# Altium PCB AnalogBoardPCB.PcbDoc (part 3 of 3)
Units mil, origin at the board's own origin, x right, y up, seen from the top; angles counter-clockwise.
Board outline 5875 x 2550 mil, 4 copper layers (Top Layer, GND, VCC, Bottom Layer); 569 components, 22 nets, 1336 pads, 360 vias.
Unrouted connection lines stored in the file: 31.
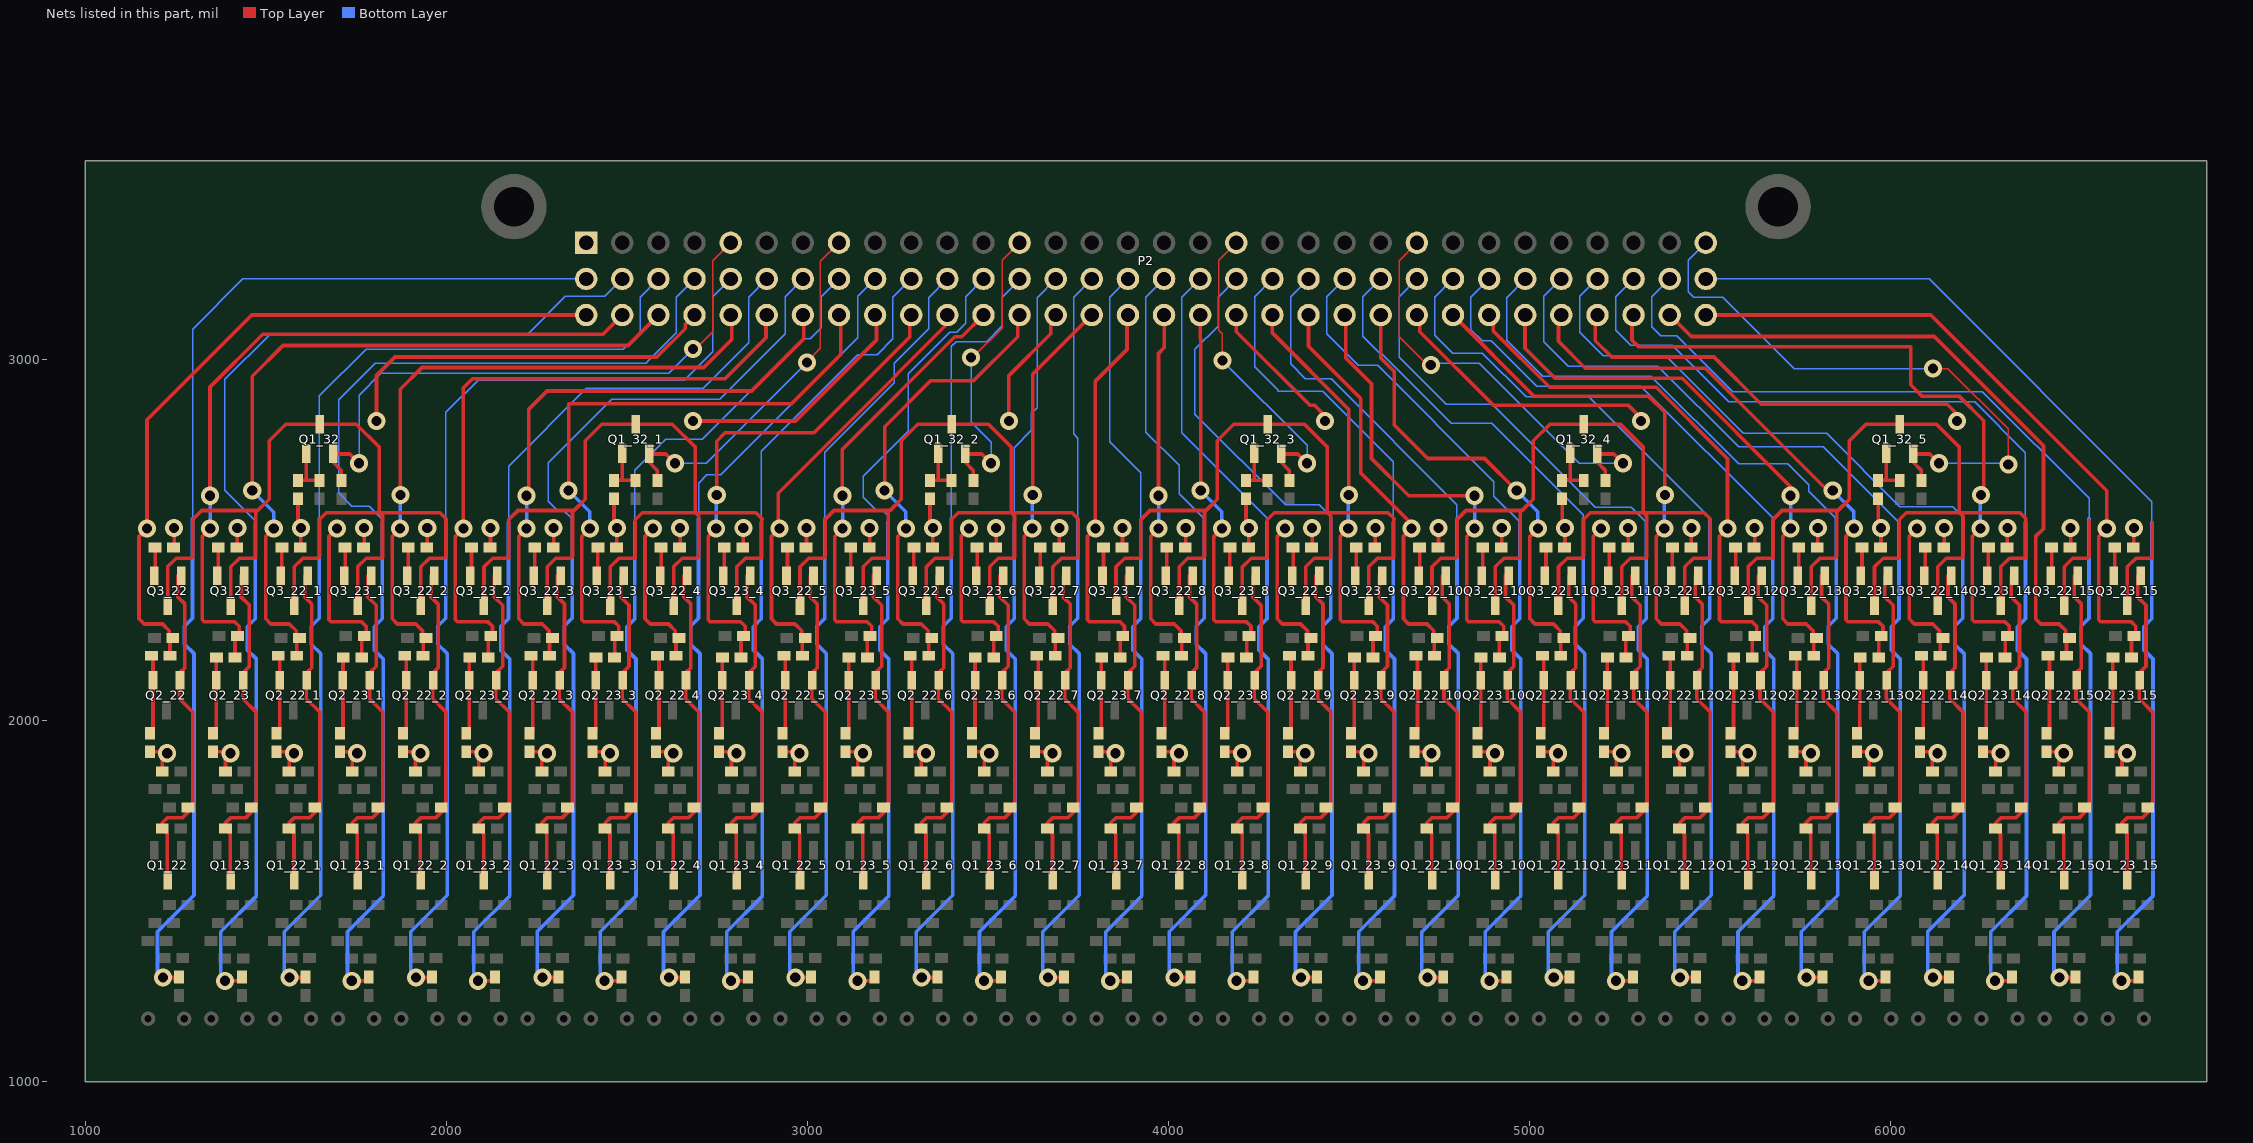
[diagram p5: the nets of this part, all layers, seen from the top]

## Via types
v1: diameter 50, hole 28, Top Layer to Bottom Layer, 327 vias
v2: diameter 50, hole 28, Top Layer to Bottom Layer, tented top, 31 vias
v3: diameter 50, hole 28, Top Layer to Bottom Layer, tented both sides, 2 vias

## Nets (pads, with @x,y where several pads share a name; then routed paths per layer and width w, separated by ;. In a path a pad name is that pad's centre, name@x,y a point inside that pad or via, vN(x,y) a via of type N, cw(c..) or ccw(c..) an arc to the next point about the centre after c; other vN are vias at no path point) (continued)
NetC4_1: C4_22.1 C4_22_1.1 C4_22_2.1 C4_22_3.1 C4_22_4.1 C4_22_5.1 C4_22_6.1 C4_22_7.1 C4_22_8.1 C4_22_9.1 C4_22_10.1 C4_22_11.1 C4_22_12.1 C4_22_13.1 C4_22_14.1 C4_22_15.1 C4_23.1 C4_23_1.1 C4_23_2.1 C4_23_3.1 C4_23_4.1 C4_23_5.1 C4_23_6.1 C4_23_7.1 C4_23_8.1 C4_23_9.1 C4_23_10.1 C4_23_11.1 C4_23_12.1 C4_23_13.1 C4_23_14.1 C4_23_15.1 Q2_22.2 Q2_22_1.2 Q2_22_2.2 Q2_22_3.2 Q2_22_4.2 Q2_22_5.2 Q2_22_6.2 Q2_22_7.2 Q2_22_8.2 Q2_22_9.2 Q2_22_10.2 Q2_22_11.2 Q2_22_12.2 Q2_22_13.2 Q2_22_14.2 Q2_22_15.2 Q2_23.2 Q2_23_1.2 Q2_23_2.2 Q2_23_3.2 Q2_23_4.2 Q2_23_5.2 Q2_23_6.2 Q2_23_7.2 Q2_23_8.2 Q2_23_9.2 Q2_23_10.2 Q2_23_11.2 Q2_23_12.2 Q2_23_13.2 Q2_23_14.2 Q2_23_15.2 R4_22.1 R4_22_1.1 R4_22_2.1 R4_22_3.1 R4_22_4.1 R4_22_5.1 R4_22_6.1 R4_22_7.1 R4_22_8.1 R4_22_9.1 R4_22_10.1 R4_22_11.1 R4_22_12.1 R4_22_13.1 R4_22_14.1 R4_22_15.1 R4_23.1 R4_23_1.1 R4_23_2.1 R4_23_3.1 R4_23_4.1 R4_23_5.1 R4_23_6.1 R4_23_7.1 R4_23_8.1 R4_23_9.1 R4_23_10.1 R4_23_11.1 R4_23_12.1 R4_23_13.1 R4_23_14.1 R4_23_15.1 | length 6080
  Top Layer w10: R4_22.1@1188.1,1973.19 1188.1,2163.19 ; R4_23.1@1363.1,1973.19 C4_23.1@1363.1,2163.19 ; R4_22_1.1@1539.1,1973.19 1539.1,2163.19 ; R4_23_1.1@1714.1,1973.19 C4_23_1.1@1714.1,2163.19 ; R4_22_2.1@1889.1,1973.19 1889.1,2163.19 ; R4_23_2.1@2064.1,1973.19 C4_23_2.1@2064.1,2163.19 ; R4_22_3.1@2239.1,1973.19 2239.1,2163.19 ; R4_23_3.1@2414.1,1973.19 C4_23_3.1@2414.1,2163.19 ; R4_22_4.1@2589.1,1973.19 2589.1,2163.19 ; R4_23_4.1@2764.1,1973.19 C4_23_4.1@2764.1,2163.19 ; R4_22_5.1@2939.1,1973.19 2939.1,2163.19 ; R4_23_5.1@3114.1,1973.19 C4_23_5.1@3114.1,2163.19 ; R4_22_6.1@3289.1,1973.19 3289.1,2163.19 ; R4_23_6.1@3464.1,1973.19 C4_23_6.1@3464.1,2163.19 ; R4_22_7.1@3639.1,1973.19 3639.1,2163.19 ; R4_23_7.1@3814.1,1973.19 C4_23_7.1@3814.1,2163.19 ; R4_22_8.1@3989.1,1973.19 3989.1,2163.19 ; R4_23_8.1@4164.1,1973.19 C4_23_8.1@4164.1,2163.19 ; R4_22_9.1@4339.1,1973.19 4339.1,2163.19 ; R4_23_9.1@4514.1,1973.19 C4_23_9.1@4514.1,2163.19 ; R4_22_10.1@4689.1,1973.19 4689.1,2163.19 ; R4_23_10.1@4864.1,1973.19 C4_23_10.1@4864.1,2163.19 ; R4_22_11.1@5039.1,1973.19 5039.1,2163.19 ; R4_23_11.1@5214.1,1973.19 C4_23_11.1@5214.1,2163.19 ; R4_22_12.1@5389.1,1973.19 5389.1,2163.19 ; R4_23_12.1@5564.1,1973.19 C4_23_12.1@5564.1,2163.19 ; R4_22_13.1@5739.1,1973.19 5739.1,2163.19 ; R4_23_13.1@5914.1,1973.19 C4_23_13.1@5914.1,2163.19 ; R4_22_14.1@6089.1,1973.19 6089.1,2163.19 ; R4_23_14.1@6264.1,1973.19 C4_23_14.1@6264.1,2163.19 ; R4_22_15.1@6439.1,1973.19 6439.1,2163.19 ; R4_23_15.1@6614.1,1973.19 C4_23_15.1@6614.1,2163.19
NetC5_1: 
NetC6_2: 
NetC7_1: 
NetC7_2: 
NetC8_1: 
NetQ1_1: Q1_32.1 Q1_32_1.1 Q1_32_2.1 Q1_32_3.1 Q1_32_4.1 Q1_32_5.1 R1_32.1 R1_32_1.1 R1_32_2.1 R1_32_3.1 R1_32_4.1 R1_32_5.1 R2_32.2 R2_32_1.2 R2_32_2.2 R2_32_3.2 R2_32_4.2 R2_32_5.2 | length 796
  Top Layer w10: R1_32.1@1589.5,2664.59 R2_32.2@1649.5,2664.59 ; 1612.5,2664.59 Q1_32.1@1612.5,2737.26 ; R1_32_1.1@2464.5,2664.59 R2_32_1.2@2524.5,2664.59 ; 2487.5,2664.59 Q1_32_1.1@2487.5,2737.26 ; R1_32_2.1@3339.5,2664.59 R2_32_2.2@3399.5,2664.59 ; 3362.5,2664.59 Q1_32_2.1@3362.5,2737.26 ; R1_32_3.1@4214.5,2664.59 R2_32_3.2@4274.5,2664.59 ; 4237.5,2664.59 Q1_32_3.1@4237.5,2737.26 ; R1_32_4.1@5089.5,2664.59 R2_32_4.2@5149.5,2664.59 ; 5112.5,2664.59 Q1_32_4.1@5112.5,2737.26 ; R1_32_5.1@5964.5,2664.59 R2_32_5.2@6024.5,2664.59 ; 5987.5,2664.59 Q1_32_5.1@5987.5,2737.26
NetQ1_3: Q1_22.3 Q1_22_1.3 Q1_22_2.3 Q1_22_3.3 Q1_22_4.3 Q1_22_5.3 Q1_22_6.3 Q1_22_7.3 Q1_22_8.3 Q1_22_9.3 Q1_22_10.3 Q1_22_11.3 Q1_22_12.3 Q1_22_13.3 Q1_22_14.3 Q1_22_15.3 Q1_23.3 Q1_23_1.3 Q1_23_2.3 Q1_23_3.3 Q1_23_4.3 Q1_23_5.3 Q1_23_6.3 Q1_23_7.3 Q1_23_8.3 Q1_23_9.3 Q1_23_10.3 Q1_23_11.3 Q1_23_12.3 Q1_23_13.3 Q1_23_14.3 Q1_23_15.3 Q2_22.1 Q2_22_1.1 Q2_22_2.1 Q2_22_3.1 Q2_22_4.1 Q2_22_5.1 Q2_22_6.1 Q2_22_7.1 Q2_22_8.1 Q2_22_9.1 Q2_22_10.1 Q2_22_11.1 Q2_22_12.1 Q2_22_13.1 Q2_22_14.1 Q2_22_15.1 Q2_23.1 Q2_23_1.1 Q2_23_2.1 Q2_23_3.1 Q2_23_4.1 Q2_23_5.1 Q2_23_6.1 Q2_23_7.1 Q2_23_8.1 Q2_23_9.1 Q2_23_10.1 Q2_23_11.1 Q2_23_12.1 Q2_23_13.1 Q2_23_14.1 Q2_23_15.1 Q3_22.1 Q3_22_1.1 Q3_22_2.1 Q3_22_3.1 Q3_22_4.1 Q3_22_5.1 Q3_22_6.1 Q3_22_7.1 Q3_22_8.1 Q3_22_9.1 Q3_22_10.1 Q3_22_11.1 Q3_22_12.1 Q3_22_13.1 Q3_22_14.1 Q3_22_15.1 Q3_23.1 Q3_23_1.1 Q3_23_2.1 Q3_23_3.1 Q3_23_4.1 Q3_23_5.1 Q3_23_6.1 Q3_23_7.1 Q3_23_8.1 Q3_23_9.1 Q3_23_10.1 Q3_23_11.1 Q3_23_12.1 Q3_23_13.1 Q3_23_14.1 Q3_23_15.1 R3_22.1 R3_22_1.1 R3_22_2.1 R3_22_3.1 R3_22_4.1 R3_22_5.1 R3_22_6.1 R3_22_7.1 R3_22_8.1 R3_22_9.1 R3_22_10.1 R3_22_11.1 R3_22_12.1 R3_22_13.1 R3_22_14.1 R3_22_15.1 R3_23.1 R3_23_1.1 R3_23_2.1 R3_23_3.1 R3_23_4.1 R3_23_5.1 R3_23_6.1 R3_23_7.1 R3_23_8.1 R3_23_9.1 R3_23_10.1 R3_23_11.1 R3_23_12.1 R3_23_13.1 R3_23_14.1 R3_23_15.1 R5_22.2 R5_22_1.2 R5_22_2.2 R5_22_3.2 R5_22_4.2 R5_22_5.2 R5_22_6.2 R5_22_7.2 R5_22_8.2 R5_22_9.2 R5_22_10.2 R5_22_11.2 R5_22_12.2 R5_22_13.2 R5_22_14.2 R5_22_15.2 R5_23.2 R5_23_1.2 R5_23_2.2 R5_23_3.2 R5_23_4.2 R5_23_5.2 R5_23_6.2 R5_23_7.2 R5_23_8.2 R5_23_9.2 R5_23_10.2 R5_23_11.2 R5_23_12.2 R5_23_13.2 R5_23_14.2 R5_23_15.2 | length 30022.3
  Top Layer w10: Q1_22.3@1227.5,1560.66 1227.5,1685.41 1213.91,1699 1213.91,1716.23 1227.68,1730 1269.5,1730 1298.5,1759 1298.5,2023 1261.5,2060 Q2_22.1@1261.5,2111.34 ; Q3_22.1@1256.9,2400.34 1256.9,2341.6 1276.5,2322 1276.5,2146 1262.9,2132.4 Q2_22.1@1262.9,2111.34 ; Q1_23.3@1402.5,1560.66 1402.5,1685.41 1388.91,1699 1388.91,1716.23 1402.68,1730 1444.5,1730 R3_23.1@1473.5,1759 ; Q3_23.1@1431.9,2400.34 1431.9,2341.6 1455.12,2318.38 1455.12,2149.62 1437.9,2132.4 Q2_23.1@1437.9,2111.34 ; Q2_23.1@1436.5,2111.34 1436.5,2060 1473.5,2023 1473.5,1772.41 R3_23.1@1460.09,1759 ; Q1_22_1.3@1578.5,1560.66 1578.5,1685.41 1564.91,1699 1564.91,1716.23 1578.68,1730 1620.5,1730 1649.5,1759 1649.5,2023 1612.5,2060 Q2_22_1.1@1612.5,2111.34 ; Q3_22_1.1@1607.9,2400.34 1607.9,2341.6 1627.5,2322 1627.5,2146 1613.9,2132.4 Q2_22_1.1@1613.9,2111.34 ; Q1_23_1.3@1753.5,1560.66 1753.5,1685.41 1739.91,1699 1739.91,1716.23 1753.68,1730 1795.5,1730 R3_23_1.1@1824.5,1759 ; Q3_23_1.1@1782.9,2400.34 1782.9,2341.6 1806.12,2318.38 1806.12,2149.62 1788.9,2132.4 Q2_23_1.1@1788.9,2111.34 ; Q2_23_1.1@1787.5,2111.34 1787.5,2060 1824.5,2023 1824.5,1772.41 R3_23_1.1@1811.09,1759 ; Q1_22_2.3@1928.5,1560.66 1928.5,1685.41 1914.91,1699 1914.91,1716.23 1928.68,1730 1970.5,1730 1999.5,1759 1999.5,2023 1962.5,2060 Q2_22_2.1@1962.5,2111.34 ; Q3_22_2.1@1957.9,2400.34 1957.9,2341.6 1977.5,2322 1977.5,2146 1963.9,2132.4 Q2_22_2.1@1963.9,2111.34 ; Q1_23_2.3@2103.5,1560.66 2103.5,1685.41 2089.91,1699 2089.91,1716.23 2103.68,1730 2145.5,1730 R3_23_2.1@2174.5,1759 ; Q3_23_2.1@2132.9,2400.34 2132.9,2341.6 2156.12,2318.38 2156.12,2149.62 2138.9,2132.4 Q2_23_2.1@2138.9,2111.34 ; Q2_23_2.1@2137.5,2111.34 2137.5,2060 2174.5,2023 2174.5,1772.41 R3_23_2.1@2161.09,1759 ; Q1_22_3.3@2278.5,1560.66 2278.5,1685.41 2264.91,1699 2264.91,1716.23 2278.68,1730 2320.5,1730 2349.5,1759 2349.5,2023 2312.5,2060 Q2_22_3.1@2312.5,2111.34 ; Q3_22_3.1@2307.9,2400.34 2307.9,2341.6 2327.5,2322 2327.5,2146 2313.9,2132.4 Q2_22_3.1@2313.9,2111.34 ; Q1_23_3.3@2453.5,1560.66 2453.5,1685.41 2439.91,1699 2439.91,1716.23 2453.68,1730 2495.5,1730 R3_23_3.1@2524.5,1759 ; Q3_23_3.1@2482.9,2400.34 2482.9,2341.6 2506.12,2318.38 2506.12,2149.62 2488.9,2132.4 Q2_23_3.1@2488.9,2111.34 ; Q2_23_3.1@2487.5,2111.34 2487.5,2060 2524.5,2023 2524.5,1772.41 R3_23_3.1@2511.09,1759 ; Q1_22_4.3@2628.5,1560.66 2628.5,1685.41 2614.91,1699 2614.91,1716.23 2628.68,1730 2670.5,1730 2699.5,1759 2699.5,2023 2662.5,2060 Q2_22_4.1@2662.5,2111.34 ; Q3_22_4.1@2657.9,2400.34 2657.9,2341.6 2677.5,2322 2677.5,2146 2663.9,2132.4 Q2_22_4.1@2663.9,2111.34 ; Q1_23_4.3@2803.5,1560.66 2803.5,1685.41 2789.91,1699 2789.91,1716.23 2803.68,1730 2845.5,1730 R3_23_4.1@2874.5,1759 ; Q3_23_4.1@2832.9,2400.34 2832.9,2341.6 2856.12,2318.38 2856.12,2149.62 2838.9,2132.4 Q2_23_4.1@2838.9,2111.34 ; Q2_23_4.1@2837.5,2111.34 2837.5,2060 2874.5,2023 2874.5,1772.41 R3_23_4.1@2861.09,1759 ; Q1_22_5.3@2978.5,1560.66 2978.5,1685.41 2964.91,1699 2964.91,1716.23 2978.68,1730 3020.5,1730 3049.5,1759 3049.5,2023 3012.5,2060 Q2_22_5.1@3012.5,2111.34 ; Q3_22_5.1@3007.9,2400.34 3007.9,2341.6 3027.5,2322 3027.5,2146 3013.9,2132.4 Q2_22_5.1@3013.9,2111.34 ; Q1_23_5.3@3153.5,1560.66 3153.5,1685.41 3139.91,1699 3139.91,1716.23 3153.68,1730 3195.5,1730 R3_23_5.1@3224.5,1759 ; Q3_23_5.1@3182.9,2400.34 3182.9,2341.6 3206.12,2318.38 3206.12,2149.62 3188.9,2132.4 Q2_23_5.1@3188.9,2111.34 ; Q2_23_5.1@3187.5,2111.34 3187.5,2060 3224.5,2023 3224.5,1772.41 R3_23_5.1@3211.09,1759 ; Q1_22_6.3@3328.5,1560.66 3328.5,1685.41 3314.91,1699 3314.91,1716.23 3328.68,1730 3370.5,1730 3399.5,1759 3399.5,2023 3362.5,2060 Q2_22_6.1@3362.5,2111.34 ; Q3_22_6.1@3357.9,2400.34 3357.9,2341.6 3377.5,2322 3377.5,2146 3363.9,2132.4 Q2_22_6.1@3363.9,2111.34 ; Q1_23_6.3@3503.5,1560.66 3503.5,1685.41 3489.91,1699 3489.91,1716.23 3503.68,1730 3545.5,1730 R3_23_6.1@3574.5,1759 ; Q3_23_6.1@3532.9,2400.34 3532.9,2341.6 3556.12,2318.38 3556.12,2149.62 3538.9,2132.4 Q2_23_6.1@3538.9,2111.34 ; Q2_23_6.1@3537.5,2111.34 3537.5,2060 3574.5,2023 3574.5,1772.41 R3_23_6.1@3561.09,1759 ; Q1_22_7.3@3678.5,1560.66 3678.5,1685.41 3664.91,1699 3664.91,1716.23 3678.68,1730 3720.5,1730 3749.5,1759 3749.5,2023 3712.5,2060 Q2_22_7.1@3712.5,2111.34 ; Q3_22_7.1@3707.9,2400.34 3707.9,2341.6 3727.5,2322 3727.5,2146 3713.9,2132.4 Q2_22_7.1@3713.9,2111.34 ; Q1_23_7.3@3853.5,1560.66 3853.5,1685.41 3839.91,1699 3839.91,1716.23 3853.68,1730 3895.5,1730 R3_23_7.1@3924.5,1759 ; Q3_23_7.1@3882.9,2400.34 3882.9,2341.6 3906.12,2318.38 3906.12,2149.62 3888.9,2132.4 Q2_23_7.1@3888.9,2111.34 ; Q2_23_7.1@3887.5,2111.34 3887.5,2060 3924.5,2023 3924.5,1772.41 R3_23_7.1@3911.09,1759 ; Q1_22_8.3@4028.5,1560.66 4028.5,1685.41 4014.91,1699 4014.91,1716.23 4028.68,1730 4070.5,1730 4099.5,1759 4099.5,2023 4062.5,2060 Q2_22_8.1@4062.5,2111.34 ; Q3_22_8.1@4057.9,2400.34 4057.9,2341.6 4077.5,2322 4077.5,2146 4063.9,2132.4 Q2_22_8.1@4063.9,2111.34 ; Q1_23_8.3@4203.5,1560.66 4203.5,1685.41 4189.91,1699 4189.91,1716.23 4203.68,1730 4245.5,1730 R3_23_8.1@4274.5,1759 ; Q3_23_8.1@4232.9,2400.34 4232.9,2341.6 4256.12,2318.38 4256.12,2149.62 4238.9,2132.4 Q2_23_8.1@4238.9,2111.34 ; Q2_23_8.1@4237.5,2111.34 4237.5,2060 4274.5,2023 4274.5,1772.41 R3_23_8.1@4261.09,1759 ; Q1_22_9.3@4378.5,1560.66 4378.5,1685.41 4364.91,1699 4364.91,1716.23 4378.68,1730 4420.5,1730 4449.5,1759 4449.5,2023 4412.5,2060 Q2_22_9.1@4412.5,2111.34 ; Q3_22_9.1@4407.9,2400.34 4407.9,2341.6 4427.5,2322 4427.5,2146 4413.9,2132.4 Q2_22_9.1@4413.9,2111.34 ; Q1_23_9.3@4553.5,1560.66 4553.5,1685.41 4539.91,1699 4539.91,1716.23 4553.68,1730 4595.5,1730 R3_23_9.1@4624.5,1759 ; Q3_23_9.1@4582.9,2400.34 4582.9,2341.6 4606.12,2318.38 4606.12,2149.62 4588.9,2132.4 Q2_23_9.1@4588.9,2111.34 ; Q2_23_9.1@4587.5,2111.34 4587.5,2060 4624.5,2023 4624.5,1772.41 R3_23_9.1@4611.09,1759 ; Q1_22_10.3@4728.5,1560.66 4728.5,1685.41 4714.91,1699 4714.91,1716.23 4728.68,1730 4770.5,1730 4799.5,1759 4799.5,2023 4762.5,2060 Q2_22_10.1@4762.5,2111.34 ; Q3_22_10.1@4757.9,2400.34 4757.9,2341.6 4777.5,2322 4777.5,2146 4763.9,2132.4 Q2_22_10.1@4763.9,2111.34 ; Q1_23_10.3@4903.5,1560.66 4903.5,1685.41 4889.91,1699 4889.91,1716.23 4903.68,1730 4945.5,1730 R3_23_10.1@4974.5,1759 ; Q3_23_10.1@4932.9,2400.34 4932.9,2341.6 4956.12,2318.38 4956.12,2149.62 4938.9,2132.4 Q2_23_10.1@4938.9,2111.34 ; Q2_23_10.1@4937.5,2111.34 4937.5,2060 4974.5,2023 4974.5,1772.41 R3_23_10.1@4961.09,1759 ; Q1_22_11.3@5078.5,1560.66 5078.5,1685.41 5064.91,1699 5064.91,1716.23 5078.68,1730 5120.5,1730 5149.5,1759 5149.5,2023 5112.5,2060 Q2_22_11.1@5112.5,2111.34 ; Q3_22_11.1@5107.9,2400.34 5107.9,2341.6 5127.5,2322 5127.5,2146 5113.9,2132.4 Q2_22_11.1@5113.9,2111.34 ; Q1_23_11.3@5253.5,1560.66 5253.5,1685.41 5239.91,1699 5239.91,1716.23 5253.68,1730 5295.5,1730 R3_23_11.1@5324.5,1759 ; Q3_23_11.1@5282.9,2400.34 5282.9,2341.6 5306.12,2318.38 5306.12,2149.62 5288.9,2132.4 Q2_23_11.1@5288.9,2111.34 ; Q2_23_11.1@5287.5,2111.34 5287.5,2060 5324.5,2023 5324.5,1772.41 R3_23_11.1@5311.09,1759 ; Q1_22_12.3@5428.5,1560.66 5428.5,1685.41 5414.91,1699 5414.91,1716.23 5428.68,1730 5470.5,1730 5499.5,1759 5499.5,2023 5462.5,2060 Q2_22_12.1@5462.5,2111.34 ; Q3_22_12.1@5457.9,2400.34 5457.9,2341.6 5477.5,2322 5477.5,2146 5463.9,2132.4 Q2_22_12.1@5463.9,2111.34 ; Q1_23_12.3@5603.5,1560.66 5603.5,1685.41 5589.91,1699 5589.91,1716.23 5603.68,1730 5645.5,1730 R3_23_12.1@5674.5,1759 ; Q3_23_12.1@5632.9,2400.34 5632.9,2341.6 5656.12,2318.38 5656.12,2149.62 5638.9,2132.4 Q2_23_12.1@5638.9,2111.34 ; Q2_23_12.1@5637.5,2111.34 5637.5,2060 5674.5,2023 5674.5,1772.41 R3_23_12.1@5661.09,1759 ; Q1_22_13.3@5778.5,1560.66 5778.5,1685.41 5764.91,1699 5764.91,1716.23 5778.68,1730 5820.5,1730 5849.5,1759 5849.5,2023 5812.5,2060 Q2_22_13.1@5812.5,2111.34 ; Q3_22_13.1@5807.9,2400.34 5807.9,2341.6 5827.5,2322 5827.5,2146 5813.9,2132.4 Q2_22_13.1@5813.9,2111.34 ; Q1_23_13.3@5953.5,1560.66 5953.5,1685.41 5939.91,1699 5939.91,1716.23 5953.68,1730 5995.5,1730 R3_23_13.1@6024.5,1759 ; Q3_23_13.1@5982.9,2400.34 5982.9,2341.6 6006.12,2318.38 6006.12,2149.62 5988.9,2132.4 Q2_23_13.1@5988.9,2111.34 ; Q2_23_13.1@5987.5,2111.34 5987.5,2060 6024.5,2023 6024.5,1772.41 R3_23_13.1@6011.09,1759 ; Q1_22_14.3@6128.5,1560.66 6128.5,1685.41 6114.91,1699 6114.91,1716.23 6128.68,1730 6170.5,1730 6199.5,1759 6199.5,2023 6162.5,2060 Q2_22_14.1@6162.5,2111.34 ; Q3_22_14.1@6157.9,2400.34 6157.9,2341.6 6177.5,2322 6177.5,2146 6163.9,2132.4 Q2_22_14.1@6163.9,2111.34 ; Q1_23_14.3@6303.5,1560.66 6303.5,1685.41 6289.91,1699 6289.91,1716.23 6303.68,1730 6345.5,1730 R3_23_14.1@6374.5,1759 ; Q3_23_14.1@6332.9,2400.34 6332.9,2341.6 6356.12,2318.38 6356.12,2149.62 6338.9,2132.4 Q2_23_14.1@6338.9,2111.34 ; Q2_23_14.1@6337.5,2111.34 6337.5,2060 6374.5,2023 6374.5,1772.41 R3_23_14.1@6361.09,1759 ; Q1_22_15.3@6478.5,1560.66 6478.5,1685.41 6464.91,1699 6464.91,1716.23 6478.68,1730 6520.5,1730 6549.5,1759 6549.5,2023 6512.5,2060 Q2_22_15.1@6512.5,2111.34 ; Q3_22_15.1@6507.9,2400.34 6507.9,2341.6 6527.5,2322 6527.5,2146 6513.9,2132.4 Q2_22_15.1@6513.9,2111.34 ; Q1_23_15.3@6653.5,1560.66 6653.5,1685.41 6639.91,1699 6639.91,1716.23 6653.68,1730 6695.5,1730 R3_23_15.1@6724.5,1759 ; Q3_23_15.1@6682.9,2400.34 6682.9,2341.6 6706.12,2318.38 6706.12,2149.62 6688.9,2132.4 Q2_23_15.1@6688.9,2111.34 ; Q2_23_15.1@6687.5,2111.34 6687.5,2060 6724.5,2023 6724.5,1772.41 R3_23_15.1@6711.09,1759
NetQ3_2: Q3_22.2 Q3_22_1.2 Q3_22_2.2 Q3_22_3.2 Q3_22_4.2 Q3_22_5.2 Q3_22_6.2 Q3_22_7.2 Q3_22_8.2 Q3_22_9.2 Q3_22_10.2 Q3_22_11.2 Q3_22_12.2 Q3_22_13.2 Q3_22_14.2 Q3_22_15.2 Q3_23.2 Q3_23_1.2 Q3_23_2.2 Q3_23_3.2 Q3_23_4.2 Q3_23_5.2 Q3_23_6.2 Q3_23_7.2 Q3_23_8.2 Q3_23_9.2 Q3_23_10.2 Q3_23_11.2 Q3_23_12.2 Q3_23_13.2 Q3_23_14.2 Q3_23_15.2 R9_22.1 R9_22_1.1 R9_22_2.1 R9_22_3.1 R9_22_4.1 R9_22_5.1 R9_22_6.1 R9_22_7.1 R9_22_8.1 R9_22_9.1 R9_22_10.1 R9_22_11.1 R9_22_12.1 R9_22_13.1 R9_22_14.1 R9_22_15.1 R9_23.1 R9_23_1.1 R9_23_2.1 R9_23_3.1 R9_23_4.1 R9_23_5.1 R9_23_6.1 R9_23_7.1 R9_23_8.1 R9_23_9.1 R9_23_10.1 R9_23_11.1 R9_23_12.1 R9_23_13.1 R9_23_14.1 R9_23_15.1 | length 2427.2
  Top Layer w10: Q3_22.2@1193.91,2403.15 R9_22.1@1193.91,2479 ; Q3_23.2@1368.91,2403.15 R9_23.1@1368.91,2479 ; Q3_22_1.2@1544.91,2403.15 R9_22_1.1@1544.91,2479 ; Q3_23_1.2@1719.91,2403.15 R9_23_1.1@1719.91,2479 ; Q3_22_2.2@1894.91,2403.15 R9_22_2.1@1894.91,2479 ; Q3_23_2.2@2069.91,2403.15 R9_23_2.1@2069.91,2479 ; Q3_22_3.2@2244.91,2403.15 R9_22_3.1@2244.91,2479 ; Q3_23_3.2@2419.91,2403.15 R9_23_3.1@2419.91,2479 ; Q3_22_4.2@2594.91,2403.15 R9_22_4.1@2594.91,2479 ; Q3_23_4.2@2769.91,2403.15 R9_23_4.1@2769.91,2479 ; Q3_22_5.2@2944.91,2403.15 R9_22_5.1@2944.91,2479 ; Q3_23_5.2@3119.91,2403.15 R9_23_5.1@3119.91,2479 ; Q3_22_6.2@3294.91,2403.15 R9_22_6.1@3294.91,2479 ; Q3_23_6.2@3469.91,2403.15 R9_23_6.1@3469.91,2479 ; Q3_22_7.2@3644.91,2403.15 R9_22_7.1@3644.91,2479 ; Q3_23_7.2@3819.91,2403.15 R9_23_7.1@3819.91,2479 ; Q3_22_8.2@3994.91,2403.15 R9_22_8.1@3994.91,2479 ; Q3_23_8.2@4169.91,2403.15 R9_23_8.1@4169.91,2479 ; Q3_22_9.2@4344.91,2403.15 R9_22_9.1@4344.91,2479 ; Q3_23_9.2@4519.91,2403.15 R9_23_9.1@4519.91,2479 ; Q3_22_10.2@4694.91,2403.15 R9_22_10.1@4694.91,2479 ; Q3_23_10.2@4869.91,2403.15 R9_23_10.1@4869.91,2479 ; Q3_22_11.2@5044.91,2403.15 R9_22_11.1@5044.91,2479 ; Q3_23_11.2@5219.91,2403.15 R9_23_11.1@5219.91,2479 ; Q3_22_12.2@5394.91,2403.15 R9_22_12.1@5394.91,2479 ; Q3_23_12.2@5569.91,2403.15 R9_23_12.1@5569.91,2479 ; Q3_22_13.2@5744.91,2403.15 R9_22_13.1@5744.91,2479 ; Q3_23_13.2@5919.91,2403.15 R9_23_13.1@5919.91,2479 ; Q3_22_14.2@6094.91,2403.15 R9_22_14.1@6094.91,2479 ; Q3_23_14.2@6269.91,2403.15 R9_23_14.1@6269.91,2479 ; Q3_22_15.2@6444.91,2403.15 R9_22_15.1@6444.91,2479 ; Q3_23_15.2@6619.91,2403.15 R9_23_15.1@6619.91,2479
NetQ4_3: 
NetQ6_2: 
SIPMBIAS1: P2.B1 P2.B2 P2.B3 P2.B4 P2.B5 P2.B6 P2.B7 P2.B8 P2.B9 P2.B10 P2.B11 P2.B12 P2.B13 P2.B14 P2.B15 P2.B16 P2.B17 P2.B18 P2.B19 P2.B20 P2.B21 P2.B22 P2.B23 P2.B24 P2.B25 P2.B26 P2.B27 P2.B28 P2.B29 P2.B30 P2.B31 P2.B32 R1_22.1 R1_22_1.1 R1_22_2.1 R1_22_3.1 R1_22_4.1 R1_22_5.1 R1_22_6.1 R1_22_7.1 R1_22_8.1 R1_22_9.1 R1_22_10.1 R1_22_11.1 R1_22_12.1 R1_22_13.1 R1_22_14.1 R1_22_15.1 R1_23.1 R1_23_1.1 R1_23_2.1 R1_23_3.1 R1_23_4.1 R1_23_5.1 R1_23_6.1 R1_23_7.1 R1_23_8.1 R1_23_9.1 R1_23_10.1 R1_23_11.1 R1_23_12.1 R1_23_13.1 R1_23_14.1 R1_23_15.1 | length 80708.6
  Top Layer w10: v1(1215.5,1288) R1_22.1@1257.91,1288 ; R1_22.1@1248.91,1279 R1_22.1@1259.5,1289.59 ; v1@1375.5,1279 1423.91,1279 R1_23.1@1434.5,1289.59 ; v1(1566.5,1288) R1_22_1.1@1608.91,1288 ; R1_22_1.1@1599.91,1279 R1_22_1.1@1610.5,1289.59 ; v1@1726.5,1279 1774.91,1279 R1_23_1.1@1785.5,1289.59 ; v1(1916.5,1288) R1_22_2.1@1958.91,1288 ; R1_22_2.1@1949.91,1279 R1_22_2.1@1960.5,1289.59 ; v1@2076.5,1279 2124.91,1279 R1_23_2.1@2135.5,1289.59 ; v1(2266.5,1288) R1_22_3.1@2308.91,1288 ; R1_22_3.1@2299.91,1279 R1_22_3.1@2310.5,1289.59 ; v1@2426.5,1279 2474.91,1279 R1_23_3.1@2485.5,1289.59 ; v1(2616.5,1288) R1_22_4.1@2658.91,1288 ; R1_22_4.1@2649.91,1279 R1_22_4.1@2660.5,1289.59 ; v1@2776.5,1279 2824.91,1279 R1_23_4.1@2835.5,1289.59 ; v1(2966.5,1288) R1_22_5.1@3008.91,1288 ; R1_22_5.1@2999.91,1279 R1_22_5.1@3010.5,1289.59 ; v1@3126.5,1279 3174.91,1279 R1_23_5.1@3185.5,1289.59 ; v1(3316.5,1288) R1_22_6.1@3358.91,1288 ; R1_22_6.1@3349.91,1279 R1_22_6.1@3360.5,1289.59 ; v1@3476.5,1279 3524.91,1279 R1_23_6.1@3535.5,1289.59 ; v1(3666.5,1288) R1_22_7.1@3708.91,1288 ; R1_22_7.1@3699.91,1279 R1_22_7.1@3710.5,1289.59 ; v1@3826.5,1279 3874.91,1279 R1_23_7.1@3885.5,1289.59 ; v1(4016.5,1288) R1_22_8.1@4058.91,1288 ; R1_22_8.1@4049.91,1279 R1_22_8.1@4060.5,1289.59 ; v1@4176.5,1279 4224.91,1279 R1_23_8.1@4235.5,1289.59 ; v1(4366.5,1288) R1_22_9.1@4408.91,1288 ; R1_22_9.1@4399.91,1279 R1_22_9.1@4410.5,1289.59 ; v1@4526.5,1279 4574.91,1279 R1_23_9.1@4585.5,1289.59 ; v1(4716.5,1288) R1_22_10.1@4758.91,1288 ; R1_22_10.1@4749.91,1279 R1_22_10.1@4760.5,1289.59 ; v1@4876.5,1279 4924.91,1279 R1_23_10.1@4935.5,1289.59 ; v1(5066.5,1288) R1_22_11.1@5108.91,1288 ; R1_22_11.1@5099.91,1279 R1_22_11.1@5110.5,1289.59 ; v1@5226.5,1279 5274.91,1279 R1_23_11.1@5285.5,1289.59 ; v1(5416.5,1288) R1_22_12.1@5458.91,1288 ; R1_22_12.1@5449.91,1279 R1_22_12.1@5460.5,1289.59 ; v1@5576.5,1279 5624.91,1279 R1_23_12.1@5635.5,1289.59 ; v1(5766.5,1288) R1_22_13.1@5808.91,1288 ; R1_22_13.1@5799.91,1279 R1_22_13.1@5810.5,1289.59 ; v1@5926.5,1279 5974.91,1279 R1_23_13.1@5985.5,1289.59 ; v1(6116.5,1288) R1_22_14.1@6158.91,1288 ; R1_22_14.1@6149.91,1279 R1_22_14.1@6160.5,1289.59 ; v1@6276.5,1279 6324.91,1279 R1_23_14.1@6335.5,1289.59 ; v1(6466.5,1288) R1_22_15.1@6508.91,1288 ; R1_22_15.1@6499.91,1279 R1_22_15.1@6510.5,1289.59 ; v1@6626.5,1279 6674.91,1279 R1_23_15.1@6685.5,1289.59
  Bottom Layer w4: 1297.5,2558 1297.5,3083.5 1436.36,3222.36 P2.B1@2387.5,3222.36 ; 1471.5,2548 1471.5,2552.5 1387,2637 1387,2944 1510,3067 2223,3067 2330,3174 2439.14,3174 P2.B2@2487.5,3222.36 ; 1648.5,2558 1648.5,2898.5 1778,3028 2490,3028 2537,3075 2537,3171.86 P2.B3@2587.5,3222.36 ; 1822.5,2548 1822.5,2557.5 1787,2593 1739,2593 1702,2630 1702,2888 1803,2989 2555,2989 2555,2991 2637,3073 2637,3171.86 P2.B4@2687.5,3222.36 ; 1998.5,2558 1998.5,2852.5 2088,2942 2659,2942 2738,3021 2738,3172.86 P2.B5@2787.5,3222.36 ; 2172.5,2548 2172.5,2703.5 2388,2919 2711,2919 2837,3045 2837,3171.86 P2.B6@2887.5,3222.36 ; 2345,2558 2348.5,2558 2324.5,2582 2307,2582 2282.5,2606.5 2282.5,2713.5 2458,2889 2757,2889 2938,3070 2938,3172.86 P2.B7@2987.5,3222.36 ; 2521,2548 2522.5,2548 2522.5,2692.5 2608,2778 2709,2778 2987.5,3056.5 3007.5,3056.5 3038,3087 3038,3172.86 P2.B8@3087.5,3222.36 ; 2698.5,2558 2698.5,2656.5 2722,2680 2760,2680 3139,3059 3139,3173.86 P2.B9@3187.5,3222.36 ; 2872.5,2548 2872.5,2745.5 3139,3012 3193,3012 3237,3056 3237,3171.86 P2.B10@3287.5,3222.36 ; 3048.5,2558 3048.5,2742.5 3241,2935 3241,2989 3336,3084 3336,3170.86 P2.B11@3387.5,3222.36 ; 3222.5,2548 3222.5,2567.5 3208,2582 3190,2582 3154,2618 3154,2676 3279,2801 3279,2960 3393.77,3074.77 3413.77,3074.77 3438,3099 3438,3172.86 P2.B12@3487.5,3222.36 ; 3398.5,2558 3398.5,3035.5 3412,3049 3496,3049 3539,3092 3539,3172 3587.5,3220.5 P2.B13@3587.5,3222.36 ; 3572.5,2548 3572.5,2755.5 3620,2803 3620,2850 3636,2866 3636,3170.86 P2.B14@3687.5,3222.36 ; 3748.5,2558 3748.5,2781.5 3737,2793 3737,3171.86 P2.B15@3787.5,3222.36 ; P2.B16@3887.5,3222.36 3837,3171.86 3837,2771 3922.5,2685.5 3922.5,2548 ; P2.B17@3987.5,3222.36 3937,3171.86 3937,2798 4029,2706 4029,2628 4098.5,2558.5 4098.5,2558 ; P2.B18@4087.5,3222.36 4037,3171.86 4036,3171.86 4036,2797 4272.5,2560.5 4272.5,2548 ; P2.B19@4187.5,3222.36 4137,3171.86 4137,3091 4073,3027 4073,2848 4324,2597 4417,2597 4448.5,2565.5 4448.5,2558 ; P2.B20@4287.5,3222.36 4238,3172.86 4238,2979 4302,2915 4302,2911 4427,2911 4622.5,2715.5 4622.5,2548 ; P2.B21@4387.5,3222.36 4338,3172.86 4338,2987 4379,2946 4450,2946 4798.5,2597.5 4798.5,2558 ; P2.B22@4487.5,3222.36 4438,3172.86 4438,3070 4525,2983 4579,2983 4901,2661 4901,2621 4972.5,2549.5 4972.5,2548 ; P2.B23@4587.5,3222.36 4538,3172.86 4538,3064 4584,3018 4587,3018 4782,2823 4895,2823 5148.5,2569.5 5148.5,2558 ; P2.B24@4687.5,3222.36 4638,3172.86 4638,3006 4769,2875 4896,2875 5181,2590 5281,2590 5322.5,2548.5 5322.5,2548 ; P2.B25@4787.5,3222.36 4737,3171.86 4737,3067 4787,3017 4869,3017 4990,2896 5163,2896 5498.5,2560.5 5498.5,2558 ; P2.B26@4887.5,3222.36 4837,3171.86 4837,3082 4868,3051 4893,3051 5019,2925 5308,2925 5672.5,2560.5 5672.5,2548 ; P2.B27@4987.5,3222.36 4936,3170.86 4936,3053 5036,2953 5335,2953 5578,2710 5714,2710 5772,2652 5772,2635 5848.5,2558.5 5848.5,2558 ; P2.B28@5087.5,3222.36 5039,3173.86 5039,3048 5106,2981 5355,2981 5579,2757 5813,2757 6022,2548 6022.5,2548 ; P2.B29@5187.5,3222.36 5139,3173.86 5139,3074 5204,3009 5377,3009 5591,2795 5822,2795 6025,2592 6171,2592 6198.5,2564.5 6198.5,2558 ; P2.B30@5287.5,3222.36 5238,3172.86 5238,3080 5280,3038 5395,3038 5551,2882 6232,2882 6372.5,2741.5 6372.5,2548 ; P2.B31@5387.5,3222.36 5338,3172.86 5338,3090 5363,3065 5407,3065 5562,2910 6253,2910 6548.5,2614.5 6548.5,2558 ; P2.B32@5487.5,3222.36 6105.64,3222.36 6722.5,2605.5 6722.5,2548
  Bottom Layer w10: v1(1215.5,1288) 1200.5,1303 1200.5,1415 1301.5,1516 1301.5,2185 1275.5,2211 1275.5,2261 1297.5,2283 1297.5,2558 ; v1@1375.5,1279 1375.5,1415 1474.5,1514 1474.5,2170 1449.5,2195 1449.5,2259 1471.5,2281 1471.5,2548 ; v1(1566.5,1288) 1551.5,1303 1551.5,1415 1652.5,1516 1652.5,2185 1626.5,2211 1626.5,2261 1648.5,2283 1648.5,2558 ; v1@1726.5,1279 1726.5,1415 1825.5,1514 1825.5,2170 1800.5,2195 1800.5,2259 1822.5,2281 1822.5,2548 ; v1(1916.5,1288) 1901.5,1303 1901.5,1415 2002.5,1516 2002.5,2185 1976.5,2211 1976.5,2261 1998.5,2283 1998.5,2558 ; v1@2076.5,1279 2076.5,1415 2175.5,1514 2175.5,2170 2150.5,2195 2150.5,2259 2172.5,2281 2172.5,2548 ; v1(2266.5,1288) 2251.5,1303 2251.5,1415 2352.5,1516 2352.5,2185 2326.5,2211 2326.5,2261 2348.5,2283 2348.5,2558 ; v1@2426.5,1279 2426.5,1415 2525.5,1514 2525.5,2170 2500.5,2195 2500.5,2259 2522.5,2281 2522.5,2548 ; v1(2616.5,1288) 2601.5,1303 2601.5,1415 2702.5,1516 2702.5,2185 2676.5,2211 2676.5,2261 2698.5,2283 2698.5,2558 ; v1@2776.5,1279 2776.5,1415 2875.5,1514 2875.5,2170 2850.5,2195 2850.5,2259 2872.5,2281 2872.5,2548 ; v1(2966.5,1288) 2951.5,1303 2951.5,1415 3052.5,1516 3052.5,2185 3026.5,2211 3026.5,2261 3048.5,2283 3048.5,2558 ; v1@3126.5,1279 3126.5,1415 3225.5,1514 3225.5,2170 3200.5,2195 3200.5,2259 3222.5,2281 3222.5,2548 ; v1(3316.5,1288) 3301.5,1303 3301.5,1415 3402.5,1516 3402.5,2185 3376.5,2211 3376.5,2261 3398.5,2283 3398.5,2558 ; v1@3476.5,1279 3476.5,1415 3575.5,1514 3575.5,2170 3550.5,2195 3550.5,2259 3572.5,2281 3572.5,2548 ; v1(3666.5,1288) 3651.5,1303 3651.5,1415 3752.5,1516 3752.5,2185 3726.5,2211 3726.5,2261 3748.5,2283 3748.5,2558 ; v1@3826.5,1279 3826.5,1415 3925.5,1514 3925.5,2170 3900.5,2195 3900.5,2259 3922.5,2281 3922.5,2548 ; v1(4016.5,1288) 4001.5,1303 4001.5,1415 4102.5,1516 4102.5,2185 4076.5,2211 4076.5,2261 4098.5,2283 4098.5,2558 ; v1@4176.5,1279 4176.5,1415 4275.5,1514 4275.5,2170 4250.5,2195 4250.5,2259 4272.5,2281 4272.5,2548 ; v1(4366.5,1288) 4351.5,1303 4351.5,1415 4452.5,1516 4452.5,2185 4426.5,2211 4426.5,2261 4448.5,2283 4448.5,2558 ; v1@4526.5,1279 4526.5,1415 4625.5,1514 4625.5,2170 4600.5,2195 4600.5,2259 4622.5,2281 4622.5,2548 ; v1(4716.5,1288) 4701.5,1303 4701.5,1415 4802.5,1516 4802.5,2185 4776.5,2211 4776.5,2261 4798.5,2283 4798.5,2558 ; v1@4876.5,1279 4876.5,1415 4975.5,1514 4975.5,2170 4950.5,2195 4950.5,2259 4972.5,2281 4972.5,2548 ; v1(5066.5,1288) 5051.5,1303 5051.5,1415 5152.5,1516 5152.5,2185 5126.5,2211 5126.5,2261 5148.5,2283 5148.5,2558 ; v1@5226.5,1279 5226.5,1415 5325.5,1514 5325.5,2170 5300.5,2195 5300.5,2259 5322.5,2281 5322.5,2548 ; v1(5416.5,1288) 5401.5,1303 5401.5,1415 5502.5,1516 5502.5,2185 5476.5,2211 5476.5,2261 5498.5,2283 5498.5,2558 ; v1@5576.5,1279 5576.5,1415 5675.5,1514 5675.5,2170 5650.5,2195 5650.5,2259 5672.5,2281 5672.5,2548 ; v1(5766.5,1288) 5751.5,1303 5751.5,1415 5852.5,1516 5852.5,2185 5826.5,2211 5826.5,2261 5848.5,2283 5848.5,2558 ; v1@5926.5,1279 5926.5,1415 6025.5,1514 6025.5,2170 6000.5,2195 6000.5,2259 6022.5,2281 6022.5,2548 ; v1(6116.5,1288) 6101.5,1303 6101.5,1415 6202.5,1516 6202.5,2185 6176.5,2211 6176.5,2261 6198.5,2283 6198.5,2558 ; v1@6276.5,1279 6276.5,1415 6375.5,1514 6375.5,2170 6350.5,2195 6350.5,2259 6372.5,2281 6372.5,2548 ; v1(6466.5,1288) 6451.5,1303 6451.5,1415 6552.5,1516 6552.5,2185 6526.5,2211 6526.5,2261 6548.5,2283 6548.5,2558 ; v1@6626.5,1279 6626.5,1415 6725.5,1514 6725.5,2170 6700.5,2195 6700.5,2259 6722.5,2281 6722.5,2548
  other v1: 1387.5,1279 1738.5,1279 2088.5,1279 2438.5,1279 2788.5,1279 3138.5,1279 3488.5,1279 3838.5,1279 4188.5,1279 4538.5,1279 4888.5,1279 5238.5,1279 5588.5,1279 5938.5,1279 6288.5,1279 6638.5,1279
SIPMOUT1: C4_22.2 C4_22_1.2 C4_22_2.2 C4_22_3.2 C4_22_4.2 C4_22_5.2 C4_22_6.2 C4_22_7.2 C4_22_8.2 C4_22_9.2 C4_22_10.2 C4_22_11.2 C4_22_12.2 C4_22_13.2 C4_22_14.2 C4_22_15.2 C4_23.2 C4_23_1.2 C4_23_2.2 C4_23_3.2 C4_23_4.2 C4_23_5.2 C4_23_6.2 C4_23_7.2 C4_23_8.2 C4_23_9.2 C4_23_10.2 C4_23_11.2 C4_23_12.2 C4_23_13.2 C4_23_14.2 C4_23_15.2 P2.C1 P2.C2 P2.C3 P2.C4 P2.C5 P2.C6 P2.C7 P2.C8 P2.C9 P2.C10 P2.C11 P2.C12 P2.C13 P2.C14 P2.C15 P2.C16 P2.C17 P2.C18 P2.C19 P2.C20 P2.C21 P2.C22 P2.C23 P2.C24 P2.C25 P2.C26 P2.C27 P2.C28 P2.C29 P2.C30 P2.C31 P2.C32 R7_22.2 R7_22_1.2 R7_22_2.2 R7_22_3.2 R7_22_4.2 R7_22_5.2 R7_22_6.2 R7_22_7.2 R7_22_8.2 R7_22_9.2 R7_22_10.2 R7_22_11.2 R7_22_12.2 R7_22_13.2 R7_22_14.2 R7_22_15.2 R7_23.2 R7_23_1.2 R7_23_2.2 R7_23_3.2 R7_23_4.2 R7_23_5.2 R7_23_6.2 R7_23_7.2 R7_23_8.2 R7_23_9.2 R7_23_10.2 R7_23_11.2 R7_23_12.2 R7_23_13.2 R7_23_14.2 R7_23_15.2 | length 46403.8
  Top Layer w10: C4_22.2@1235.09,2179 1235.09,2228 1233.5,2229.59 1233.5,2248 1214.5,2267 1163.5,2267 1149.5,2281 1149.5,2509 v1(1171.5,2531) 1171.5,2832.5 1461.36,3122.36 P2.C1@2387.5,3122.36 ; v1(1346,2622) 1346,2923 1492,3069 2434.14,3069 P2.C2@2487.5,3122.36 ; v1(1346.5,2531) 1324.5,2509 1324.5,2279 1330.86,2272.64 1414.86,2272.64 1427.09,2260.41 1427.09,2234 1415.09,2222 C4_23.2@1415.09,2174 ; v1(1463,2636) 1463,2953 1548,3038 2503.14,3038 P2.C3@2587.5,3122.36 ; v1(1522.5,2531) 1500.5,2509 1500.5,2281 1514.5,2267 1565.5,2267 1584.5,2248 1584.5,2229.59 1586.09,2228 C4_22_1.2@1586.09,2179 ; v1(1697.5,2531) 1675.5,2509 1675.5,2279 1681.86,2272.64 1765.86,2272.64 1778.09,2260.41 1778.09,2234 1766.09,2222 C4_23_1.2@1766.09,2174 ; v1(1807,2829) 1807,2955 1858,3006 2583,3006 2661.45,3084.45 2661.45,3096.31 P2.C4@2687.5,3122.36 ; v1(1872.5,2531) 1850.5,2509 1850.5,2281 1864.5,2267 1915.5,2267 1934.5,2248 1934.5,2229.59 1936.09,2228 C4_22_2.2@1936.09,2179 ; v1(1873,2624) 1873,2917 1933,2977 2713,2977 2790.4,3054.4 P2.C5@2790.4,3119.46 ; C4_23_2.2@2116.09,2174 2116.09,2222 2128.09,2234 2128.09,2260.41 2115.86,2272.64 2031.86,2272.64 2025.5,2279 2025.5,2509 v1(2047.5,2531) 2047.5,2920.5 2073,2946 2772,2946 2885.4,3059.4 P2.C6@2885.4,3120.27 ; v1(2222.5,2531) 2200.5,2509 2200.5,2281 2214.5,2267 2265.5,2267 2284.5,2248 2284.5,2229.59 2286.09,2228 C4_22_3.2@2286.09,2179 ; v1@2229,2629 2229,2862 2279,2912 2846,2912 2989.4,3055.4 P2.C7@2989.4,3120.46 ; v1(2339,2636) 2339,2877 2956,2877 3092,3013 P2.C8@3092,3117.86 ; v1(2397.5,2531) 2375.5,2509 2375.5,2279 2381.86,2272.64 2465.86,2272.64 2478.09,2260.41 2478.09,2234 2466.09,2222 C4_23_3.2@2466.09,2174 ; v1(2572.5,2531) 2550.5,2509 2550.5,2281 2564.5,2267 2615.5,2267 2634.5,2248 2634.5,2229.59 2636.09,2228 C4_22_4.2@2636.09,2179 ; v1(2683,2829) 2967,2829 3191.4,3053.4 P2.C9@3191.4,3118.46 ; v1(2747.5,2531) 2725.5,2509 2725.5,2279 2731.86,2272.64 2815.86,2272.64 2828.09,2260.41 2828.09,2234 2816.09,2222 C4_23_4.2@2816.09,2174 ; v1(2749,2624) 2749,2773 2772,2796 3018,2796 3283.4,3061.4 P2.C10@3283.4,3118.27 ; v1@2919,2539 2919,2629 3246,2956 3246,2957 3387.5,3098.5 P2.C11@3387.5,3122.36 ; v1(2922.5,2531) 2900.5,2509 2900.5,2281 2914.5,2267 2965.5,2267 2984.5,2248 2984.5,2229.59 2986.09,2228 C4_22_5.2@2986.09,2179 ; v1@3089,2622 v1(3097,2622) 3097,2751 3408,3062 3427.14,3062 P2.C12@3487.5,3122.36 ; v1(3097.5,2531) 3075.5,2509 3075.5,2279 3081.86,2272.64 3165.86,2272.64 3178.09,2260.41 3178.09,2234 3166.09,2222 C4_23_5.2@3166.09,2174 ; v1(3214,2636) 3214,2813 3341,2940 3460,2940 3582.4,3062.4 P2.C13@3582.4,3117.27 ; v1(3272.5,2531) 3250.5,2509 3250.5,2281 3264.5,2267 3315.5,2267 3334.5,2248 3334.5,2229.59 3336.09,2228 C4_22_6.2@3336.09,2179 ; v1(3447.5,2531) 3425.5,2509 3425.5,2279 3431.86,2272.64 3515.86,2272.64 3528.09,2260.41 3528.09,2234 3516.09,2222 C4_23_6.2@3516.09,2174 ; v1(3558,2829) 3558,2955 3673.9,3070.9 3673.9,3108.77 P2.C14@3687.5,3122.36 ; v1(3622.5,2531) 3600.5,2509 3600.5,2281 3614.5,2267 3665.5,2267 3684.5,2248 3684.5,2229.59 3686.09,2228 C4_22_7.2@3686.09,2179 ; v1(3624,2624) 3624,2958.86 P2.C15@3787.5,3122.36 ; C4_23_7.2@3866.09,2174 3866.09,2222 3878.09,2234 3878.09,2260.41 3865.86,2272.64 3781.86,2272.64 3775.5,2279 3775.5,2509 v1(3797.5,2531) 3797.5,2939.5 3885,3027 P2.C16@3885,3119.86 ; v1@3953,2622 v1(3972,2622) 3972,3016 3987.5,3031.5 P2.C17@3987.5,3122.36 ; v1(3972.5,2531) 3950.5,2509 3950.5,2281 3964.5,2267 4015.5,2267 4034.5,2248 4034.5,2229.59 4036.09,2228 C4_22_8.2@4036.09,2179 ; P2.C18@4087.5,3122.36 4087.5,3058.5 4089,3057 v1(4089,2636) ; v1(4147.5,2531) 4125.5,2509 4125.5,2279 4131.86,2272.64 4215.86,2272.64 4228.09,2260.41 4228.09,2234 4216.09,2222 C4_23_8.2@4216.09,2174 ; P2.C19@4187.5,3122.36 4187.5,3076.36 4390.86,2873 4403,2873 4433,2843 v1(4433,2829) ; P2.C20@4287.5,3122.36 4287.5,3072.5 4499,2861 v1(4499,2624) ; v1(4322.5,2531) 4300.5,2509 4300.5,2281 4314.5,2267 4365.5,2267 4384.5,2248 4384.5,2229.59 4386.09,2228 C4_22_9.2@4386.09,2179 ; P2.C21@4387.5,3122.36 4387.5,3035.5 4532,2891 4532,2685 4672.5,2544.5 v1(4672.5,2531) 4650.5,2509 4650.5,2281 4664.5,2267 4715.5,2267 4734.5,2248 4734.5,2229.59 4736.09,2228 C4_22_10.2@4736.09,2179 ; P2.C22@4491,3118.86 4491,3003 4562,2932 4562,2725 4665,2622 v1(4847,2622) ; v1(4497.5,2531) 4475.5,2509 4475.5,2279 4481.86,2272.64 4565.86,2272.64 4578.09,2260.41 4578.09,2234 4566.09,2222 C4_23_9.2@4566.09,2174 ; P2.C23@4587.5,3122.36 4587.5,3003.5 4625,2966 4625,2818 4717.75,2725.25 4874.75,2725.25 v1(4964,2636) ; P2.C24@4687.5,3122.36 4695.64,3114.22 4695.64,3076.36 4899,2873 5272,2873 5308,2837 v1(5308,2829) ; P2.C25@4787.5,3122.36 5012.86,2897 5330,2897 5374,2853 v1(5374,2624) ; v1(4847.5,2531) 4825.5,2509 4825.5,2279 4831.86,2272.64 4915.86,2272.64 4928.09,2260.41 4928.09,2234 4916.09,2222 C4_23_10.2@4916.09,2174 ; P2.C26@4887.5,3122.36 4899.14,3110.72 4899.14,3077.86 5055,2922 5350,2922 5547.5,2724.5 v1(5547.5,2531) 5525.5,2509 5525.5,2279 5531.86,2272.64 5615.86,2272.64 5628.09,2260.41 5628.09,2234 5616.09,2222 C4_23_12.2@5616.09,2174 ; P2.C27@4987,3121.86 4987,3030 5070,2947 5422,2947 5722,2647 v1(5722,2622) ; v1(5022.5,2531) 5000.5,2509 5000.5,2281 5014.5,2267 5065.5,2267 5084.5,2248 5084.5,2229.59 5086.09,2228 C4_22_11.2@5086.09,2179 ; P2.C28@5079.6,3114.46 5079.6,3049.4 5154,2975 5486,2975 5825,2636 v1(5839,2636) ; P2.C29@5181.6,3116.46 5181.6,3051.4 5227,3006 5510,3006 5641,2875 6156,2875 6183,2848 v1(6183,2829) ; v1(5197.5,2531) 5175.5,2509 5175.5,2279 5181.86,2272.64 5265.86,2272.64 5278.09,2260.41 5278.09,2234 5266.09,2222 C4_23_11.2@5266.09,2174 ; P2.C30@5283.1,3117.96 5283.1,3052.9 5301,3035 6055,3035 6055,2929 6087,2897 6190,2897 6257,2830 v1@6257,2621 ; v1(5372.5,2531) 5350.5,2509 5350.5,2281 5364.5,2267 5415.5,2267 5434.5,2248 5434.5,2229.59 5436.09,2228 C4_22_12.2@5436.09,2179 ; P2.C31@5387.5,3122.36 5446.86,3063 6120,3063 6422.5,2760.5 6422.5,2531 6400.5,2509 6400.5,2281 6414.5,2267 6465.5,2267 6484.5,2248 6484.5,2229.59 6486.09,2228 C4_22_15.2@6486.09,2179 ; P2.C32@5487.5,3122.36 6110.64,3122.36 6597.5,2635.5 v1(6597.5,2531) 6575.5,2509 6575.5,2279 6581.86,2272.64 6665.86,2272.64 6678.09,2260.41 6678.09,2234 6666.09,2222 C4_23_15.2@6666.09,2174 ; v1(5722.5,2531) 5700.5,2509 5700.5,2281 5714.5,2267 5765.5,2267 5784.5,2248 5784.5,2229.59 5786.09,2228 C4_22_13.2@5786.09,2179 ; v1(5897.5,2531) 5875.5,2509 5875.5,2279 5881.86,2272.64 5965.86,2272.64 5978.09,2260.41 5978.09,2234 5966.09,2222 C4_23_13.2@5966.09,2174 ; v1(6072.5,2531) 6050.5,2509 6050.5,2281 6064.5,2267 6115.5,2267 6134.5,2248 6134.5,2229.59 6136.09,2228 C4_22_14.2@6136.09,2179 ; v1(6247.5,2531) 6225.5,2509 6225.5,2279 6231.86,2272.64 6315.86,2272.64 6328.09,2260.41 6328.09,2234 6316.09,2222 C4_23_14.2@6316.09,2174
  Bottom Layer w10: v1(1346,2622) 1346.5,2621.5 v1(1346.5,2531) ; v1(1463,2636) 1522.5,2576.5 v1(1522.5,2531) ; v1(1872.5,2531) v1@1872.5,2623.5 ; v1(2222.5,2531) v1@2222.5,2621.5 ; v1(2339,2636) 2397.5,2577.5 v1(2397.5,2531) ; v1(2747.5,2531) v1@2747.5,2622.5 ; v1(3097.5,2531) v1@3097.5,2621.5 ; v1(3214,2636) 3272.5,2577.5 v1(3272.5,2531) ; v1(3622.5,2531) v1@3622.5,2622.5 ; v1(3972,2622) 3972.5,2621.5 v1(3972.5,2531) ; v1(4089,2636) 4147.5,2577.5 v1(4147.5,2531) ; v1(4497.5,2531) v1@4497.5,2622.5 ; v1(4847.5,2531) v1@4847.5,2621.5 ; v1(4964,2636) 5022.5,2577.5 v1(5022.5,2531) ; v1(5372.5,2531) 5372.5,2622.5 v1(5374,2624) ; v1@5716,2627 5722.5,2620.5 v1(5722.5,2531) ; v1(5839,2636) 5897.5,2577.5 v1(5897.5,2531) ; v1(6247.5,2531) 6247.5,2622.5 v1(6249,2624)
  other v1: 2222,2622
SIPMOUT2: 
SUMMED1: P2.A5 P2.A8 P2.A13 P2.A19 P2.A24 P2.A32 Q1_32.2 Q1_32_1.2 Q1_32_2.2 Q1_32_3.2 Q1_32_4.2 Q1_32_5.2 R3_32.2 R3_32_1.2 R3_32_2.2 R3_32_3.2 R3_32_4.2 R3_32_5.2 | length 7312.3
  Top Layer w4: v3(2683,3028) 2690,3028 2738,3076 2738,3272.86 P2.A5@2787.5,3322.36 ; v1@2999,2993 3036,3030 3036,3270.86 P2.A8@3087.5,3322.36 ; v1(3453,3005) 3458,3005 3539,3086 3539,3273.86 P2.A13@3587.5,3322.36 ; v1(4149,2996) 4149,3070 4139,3080 4139,3273.86 P2.A19@4187.5,3322.36 ; P2.A24@4687.5,3322.36 4638,3272.86 4638,3062 4716,2984 v1(4726,2984) ; v1(6116,2974) 6158,2974 6325,2807 v3(6325,2709)
  Top Layer w10: R3_32.2@1709.5,2664.59 1709.5,2692 1686.9,2714.6 Q1_32.2@1686.9,2737.66 1732.84,2737.66 v1(1758.5,2712) ; R3_32_1.2@2584.5,2664.59 2584.5,2692 2561.9,2714.6 Q1_32_1.2@2561.9,2737.66 2607.84,2737.66 v1(2633.5,2712) ; R3_32_2.2@3459.5,2664.59 3459.5,2692 3436.9,2714.6 Q1_32_2.2@3436.9,2737.66 3482.84,2737.66 v1(3508.5,2712) ; R3_32_3.2@4334.5,2664.59 4334.5,2692 4311.9,2714.6 Q1_32_3.2@4311.9,2737.66 4357.84,2737.66 v1(4383.5,2712) ; R3_32_4.2@5209.5,2664.59 5209.5,2692 5186.9,2714.6 Q1_32_4.2@5186.9,2737.66 5232.84,2737.66 v1(5258.5,2712) ; R3_32_5.2@6084.5,2664.59 6084.5,2692 6061.9,2714.6 Q1_32_5.2@6061.9,2737.66 6107.84,2737.66 v1(6133.5,2712)
  Bottom Layer w4: v1(1758.5,2712) 1758.5,2900.5 1819,2961 2616,2961 v3(2683,3028) ; v1(2633.5,2712) 2720,2712 v1(2999,2991) ; v1(3453,3005) 3453,2825 3508.5,2769.5 v1(3508.5,2712) ; v1(4149,2996) 4383.5,2761.5 v1(4383.5,2712) ; v1@4718,2989 4860,2989 5137,2712 v1(5258.5,2712) ; P2.A32@5487.5,3322.36 5439,3273.86 5439,3187 5454,3172 5535,3172 5733,2974 v1(6116,2974) ; v1(6133.5,2712) 6322,2712 v3(6325,2709)
SUMMING1: Q1_32.3 Q1_32_1.3 Q1_32_2.3 Q1_32_3.3 Q1_32_4.3 Q1_32_5.3 Q3_22.3 Q3_22_1.3 Q3_22_2.3 Q3_22_3.3 Q3_22_4.3 Q3_22_5.3 Q3_22_6.3 Q3_22_7.3 Q3_22_8.3 Q3_22_9.3 Q3_22_10.3 Q3_22_11.3 Q3_22_12.3 Q3_22_13.3 Q3_22_14.3 Q3_22_15.3 Q3_23.3 Q3_23_1.3 Q3_23_2.3 Q3_23_3.3 Q3_23_4.3 Q3_23_5.3 Q3_23_6.3 Q3_23_7.3 Q3_23_8.3 Q3_23_9.3 Q3_23_10.3 Q3_23_11.3 Q3_23_12.3 Q3_23_13.3 Q3_23_14.3 Q3_23_15.3 | length 17342
  Top Layer w10: Q3_22.3@1228.5,2317.66 1228.5,2425 1252.5,2449 1293.5,2449 1298.5,2454 1298.5,2556 1323.5,2581 1478.5,2581 1510.08,2612.58 1510.08,2774.58 1555.84,2820.34 1751.16,2820.34 1814.5,2757 1814.5,2575 1823.5,2566 1823.5,2451 1819.5,2449 1778.5,2449 1754.5,2425 Q3_23_1.3@1754.5,2317.66 ; Q3_23.3@1403.5,2317.66 1403.5,2425 1427.5,2449 1468.5,2449 1472.5,2451 1472.5,2580 ; Q3_22_1.3@1579.5,2317.66 1579.5,2425 1603.5,2449 1644.5,2449 1649.5,2454 1649.5,2557 1667.5,2575 1982.5,2575 1999.5,2558 1999.5,2454 1994.5,2449 1953.5,2449 1929.5,2425 Q3_22_2.3@1929.5,2317.66 ; Q3_23_2.3@2104.5,2317.66 2104.5,2425 2128.5,2449 2169.5,2449 2173.5,2451 2173.5,2556 2198.5,2581 2353.5,2581 2385.08,2612.58 2385.08,2774.58 2430.84,2820.34 2626.16,2820.34 2689.5,2757 2689.5,2575 2699.5,2565 2699.5,2454 2694.5,2449 2653.5,2449 2629.5,2425 Q3_22_4.3@2629.5,2317.66 ; Q3_22_3.3@2279.5,2317.66 2279.5,2425 2303.5,2449 2344.5,2449 2349.5,2454 2349.5,2577 ; Q3_23_3.3@2454.5,2317.66 2454.5,2425 2478.5,2449 2519.5,2449 2523.5,2451 2523.5,2556 ; 2524.5,2557 2542.5,2575 2857.5,2575 2874.5,2558 2873.5,2557 2873.5,2451 2869.5,2449 2828.5,2449 2804.5,2425 Q3_23_4.3@2804.5,2317.66 ; Q3_22_5.3@2979.5,2317.66 2979.5,2425 3003.5,2449 3044.5,2449 3049.5,2454 3049.5,2554 ; 3048.5,2556 3073.5,2581 3228.5,2581 3260.08,2612.58 3260.08,2774.58 3305.84,2820.34 3501.16,2820.34 3564.5,2757 3564.5,2575 3573.5,2566 3573.5,2451 3569.5,2449 3528.5,2449 3504.5,2425 Q3_23_6.3@3504.5,2317.66 ; Q3_23_5.3@3154.5,2317.66 3154.5,2425 3178.5,2449 3219.5,2449 3223.5,2451 3223.5,2576 ; Q3_22_6.3@3329.5,2317.66 3329.5,2425 3353.5,2449 3394.5,2449 3399.5,2454 3399.5,2557 3417.5,2575 3732.5,2575 3749.5,2558 ; Q3_22_7.3@3679.5,2317.66 3679.5,2425 3703.5,2449 3744.5,2449 3749.5,2454 3749.5,2554 ; Q3_23_7.3@3854.5,2317.66 3854.5,2425 3878.5,2449 3919.5,2449 3923.5,2451 3923.5,2556 3948.5,2581 4103.5,2581 4135.08,2612.58 4135.08,2774.58 4180.84,2820.34 4376.16,2820.34 4439.5,2757 4439.5,2575 4449.5,2565 4449.5,2454 4444.5,2449 4403.5,2449 4379.5,2425 Q3_22_9.3@4379.5,2317.66 ; Q3_22_8.3@4029.5,2317.66 4029.5,2425 4053.5,2449 4094.5,2449 4099.5,2454 4099.5,2577 ; Q3_23_8.3@4204.5,2317.66 4204.5,2425 4228.5,2449 4269.5,2449 4273.5,2451 4273.5,2556 ; 4274.5,2557 4292.5,2575 4607.5,2575 4624.5,2558 ; Q3_23_9.3@4554.5,2317.66 4554.5,2425 4578.5,2449 4619.5,2449 4623.5,2451 4623.5,2557 ; Q3_22_10.3@4729.5,2317.66 4729.5,2425 4753.5,2449 4794.5,2449 4799.5,2454 4799.5,2555 4798.5,2556 4823.5,2581 4978.5,2581 5010.08,2612.58 5010.08,2774.58 5055.84,2820.34 5251.16,2820.34 5314.5,2757 5314.5,2575 5323.5,2566 5323.5,2451 5319.5,2449 5278.5,2449 5254.5,2425 Q3_23_11.3@5254.5,2317.66 ; Q3_23_10.3@4904.5,2317.66 4904.5,2425 4928.5,2449 4969.5,2449 4973.5,2451 4973.5,2576 ; Q3_22_11.3@5079.5,2317.66 5079.5,2425 5103.5,2449 5144.5,2449 5149.5,2454 5149.5,2554 ; 5149.5,2557 5167.5,2575 5482.5,2575 5499.5,2558 ; Q3_22_12.3@5429.5,2317.66 5429.5,2425 5453.5,2449 5494.5,2449 5499.5,2454 5499.5,2554 ; Q3_23_12.3@5604.5,2317.66 5604.5,2425 5628.5,2449 5669.5,2449 5673.5,2451 5673.5,2556 5698.5,2581 5853.5,2581 5885.08,2612.58 5885.08,2774.58 5930.84,2820.34 6126.16,2820.34 6189.5,2757 6189.5,2575 6198.5,2566 ; Q3_22_13.3@5779.5,2317.66 5779.5,2425 5803.5,2449 5844.5,2449 5849.5,2454 5849.5,2577 ; Q3_23_13.3@5954.5,2317.66 5954.5,2425 5978.5,2449 6019.5,2449 6023.5,2451 6023.5,2556 ; 6024.5,2557 6042.5,2575 6357.5,2575 6373.5,2559 6373.5,2451 6369.5,2449 6328.5,2449 6304.5,2425 Q3_23_14.3@6304.5,2317.66 ; Q3_22_14.3@6129.5,2317.66 6129.5,2425 6153.5,2449 6194.5,2449 6199.5,2454 6199.5,2565 ; Q3_22_15.3@6479.5,2317.66 6479.5,2425 6503.5,2449 6544.5,2449 6549.5,2454 6549.5,2554 ; Q3_23_15.3@6654.5,2317.66 6654.5,2425 6678.5,2449 6719.5,2449 6723.5,2451 6723.5,2547
VCC: P2.A1 R1_32.2 R1_32_1.2 R1_32_2.2 R1_32_3.2 R1_32_4.2 R1_32_5.2 R2_22.2 R2_22_1.2 R2_22_2.2 R2_22_3.2 R2_22_4.2 R2_22_5.2 R2_22_6.2 R2_22_7.2 R2_22_8.2 R2_22_9.2 R2_22_10.2 R2_22_11.2 R2_22_12.2 R2_22_13.2 R2_22_14.2 R2_22_15.2 R2_23.2 R2_23_1.2 R2_23_2.2 R2_23_3.2 R2_23_4.2 R2_23_5.2 R2_23_6.2 R2_23_7.2 R2_23_8.2 R2_23_9.2 R2_23_10.2 R2_23_11.2 R2_23_12.2 R2_23_13.2 R2_23_14.2 R2_23_15.2 R4_22.2 R4_22_1.2 R4_22_2.2 R4_22_3.2 R4_22_4.2 R4_22_5.2 R4_22_6.2 R4_22_7.2 R4_22_8.2 R4_22_9.2 R4_22_10.2 R4_22_11.2 R4_22_12.2 R4_22_13.2 R4_22_14.2 R4_22_15.2 R4_23.2 R4_23_1.2 R4_23_2.2 R4_23_3.2 R4_23_4.2 R4_23_5.2 R4_23_6.2 R4_23_7.2 R4_23_8.2 R4_23_9.2 R4_23_10.2 R4_23_11.2 R4_23_12.2 R4_23_13.2 R4_23_14.2 R4_23_15.2 R9_22.2 R9_22_1.2 R9_22_2.2 R9_22_3.2 R9_22_4.2 R9_22_5.2 R9_22_6.2 R9_22_7.2 R9_22_8.2 R9_22_9.2 R9_22_10.2 R9_22_11.2 R9_22_12.2 R9_22_13.2 R9_22_14.2 R9_22_15.2 R9_23.2 R9_23_1.2 R9_23_2.2 R9_23_3.2 R9_23_4.2 R9_23_5.2 R9_23_6.2 R9_23_7.2 R9_23_8.2 R9_23_9.2 R9_23_10.2 R9_23_11.2 R9_23_12.2 R9_23_13.2 R9_23_14.2 R9_23_15.2 | length 5386.4
  Top Layer w10: R4_22.2@1179.5,1913.41 1223.09,1913.41 1213.91,1904.23 R2_22.2@1213.91,1859 ; R9_22.2@1246.5,2480.41 v1(1246.5,2533) ; R4_23.2@1354.5,1913.41 1398.09,1913.41 1388.91,1904.23 R2_23.2@1388.91,1859 ; R9_23.2@1421.5,2480.41 v1(1421.5,2533) ; R4_22_1.2@1530.5,1913.41 1574.09,1913.41 1564.91,1904.23 R2_22_1.2@1564.91,1859 ; R1_32.2@1589.5,2613.41 1589.5,2541 v1(1597.5,2533) R9_22_1.2@1597.5,2480.41 ; R4_23_1.2@1705.5,1913.41 1749.09,1913.41 1739.91,1904.23 R2_23_1.2@1739.91,1859 ; R9_23_1.2@1772.5,2480.41 v1(1772.5,2533) ; R4_22_2.2@1880.5,1913.41 1924.09,1913.41 1914.91,1904.23 R2_22_2.2@1914.91,1859 ; R9_22_2.2@1947.5,2480.41 v1(1947.5,2533) ; R4_23_2.2@2055.5,1913.41 2099.09,1913.41 2089.91,1904.23 R2_23_2.2@2089.91,1859 ; R9_23_2.2@2122.5,2480.41 v1(2122.5,2533) ; R4_22_3.2@2230.5,1913.41 2274.09,1913.41 2264.91,1904.23 R2_22_3.2@2264.91,1859 ; R9_22_3.2@2297.5,2480.41 v1(2297.5,2533) ; R4_23_3.2@2405.5,1913.41 2449.09,1913.41 2439.91,1904.23 R2_23_3.2@2439.91,1859 ; v1@2464.5,2541 R1_32_1.2@2464.5,2613.41 ; R9_23_3.2@2472.5,2480.41 v1(2472.5,2533) ; R4_22_4.2@2580.5,1913.41 2624.09,1913.41 2614.91,1904.23 R2_22_4.2@2614.91,1859 ; R9_22_4.2@2647.5,2480.41 v1(2647.5,2533) ; R4_23_4.2@2755.5,1913.41 2799.09,1913.41 2789.91,1904.23 R2_23_4.2@2789.91,1859 ; R9_23_4.2@2822.5,2480.41 v1(2822.5,2533) ; R4_22_5.2@2930.5,1913.41 2974.09,1913.41 2964.91,1904.23 R2_22_5.2@2964.91,1859 ; R9_22_5.2@2997.5,2480.41 v1(2997.5,2533) ; R4_23_5.2@3105.5,1913.41 3149.09,1913.41 3139.91,1904.23 R2_23_5.2@3139.91,1859 ; R9_23_5.2@3172.5,2480.41 v1(3172.5,2533) ; R4_22_6.2@3280.5,1913.41 3324.09,1913.41 3314.91,1904.23 R2_22_6.2@3314.91,1859 ; v1@3339.5,2541 R1_32_2.2@3339.5,2613.41 ; R9_22_6.2@3347.5,2480.41 v1(3347.5,2533) ; R4_23_6.2@3455.5,1913.41 3499.09,1913.41 3489.91,1904.23 R2_23_6.2@3489.91,1859 ; R9_23_6.2@3522.5,2480.41 v1(3522.5,2533) ; R4_22_7.2@3630.5,1913.41 3674.09,1913.41 3664.91,1904.23 R2_22_7.2@3664.91,1859 ; R9_22_7.2@3697.5,2480.41 v1(3697.5,2533) ; R4_23_7.2@3805.5,1913.41 3849.09,1913.41 3839.91,1904.23 R2_23_7.2@3839.91,1859 ; R9_23_7.2@3872.5,2480.41 v1(3872.5,2533) ; R4_22_8.2@3980.5,1913.41 4024.09,1913.41 4014.91,1904.23 R2_22_8.2@4014.91,1859 ; R9_22_8.2@4047.5,2480.41 v1(4047.5,2533) ; R4_23_8.2@4155.5,1913.41 4199.09,1913.41 4189.91,1904.23 R2_23_8.2@4189.91,1859 ; v1@4214.5,2541 R1_32_3.2@4214.5,2613.41 ; R9_23_8.2@4222.5,2480.41 v1(4222.5,2533) ; R4_22_9.2@4330.5,1913.41 4374.09,1913.41 4364.91,1904.23 R2_22_9.2@4364.91,1859 ; R9_22_9.2@4397.5,2480.41 v1(4397.5,2533) ; R4_23_9.2@4505.5,1913.41 4549.09,1913.41 4539.91,1904.23 R2_23_9.2@4539.91,1859 ; R9_23_9.2@4572.5,2480.41 v1(4572.5,2533) ; R4_22_10.2@4680.5,1913.41 4724.09,1913.41 4714.91,1904.23 R2_22_10.2@4714.91,1859 ; R9_22_10.2@4747.5,2480.41 v1(4747.5,2533) ; R4_23_10.2@4855.5,1913.41 4899.09,1913.41 4889.91,1904.23 R2_23_10.2@4889.91,1859 ; R9_23_10.2@4922.5,2480.41 v1(4922.5,2533) ; R4_22_11.2@5030.5,1913.41 5074.09,1913.41 5064.91,1904.23 R2_22_11.2@5064.91,1859 ; v1@5089.5,2541 R1_32_4.2@5089.5,2613.41 ; R9_22_11.2@5097.5,2480.41 v1(5097.5,2533) ; R4_23_11.2@5205.5,1913.41 5249.09,1913.41 5239.91,1904.23 R2_23_11.2@5239.91,1859 ; R9_23_11.2@5272.5,2480.41 v1(5272.5,2533) ; R4_22_12.2@5380.5,1913.41 5424.09,1913.41 5414.91,1904.23 R2_22_12.2@5414.91,1859 ; R9_22_12.2@5447.5,2480.41 v1(5447.5,2533) ; R4_23_12.2@5555.5,1913.41 5599.09,1913.41 5589.91,1904.23 R2_23_12.2@5589.91,1859 ; R9_23_12.2@5622.5,2480.41 v1(5622.5,2533) ; R4_22_13.2@5730.5,1913.41 5774.09,1913.41 5764.91,1904.23 R2_22_13.2@5764.91,1859 ; R9_22_13.2@5797.5,2480.41 v1(5797.5,2533) ; R4_23_13.2@5905.5,1913.41 5949.09,1913.41 5939.91,1904.23 R2_23_13.2@5939.91,1859 ; v1@5964.5,2541 R1_32_5.2@5964.5,2613.41 ; R9_23_13.2@5972.5,2480.41 v1(5972.5,2533) ; R4_22_14.2@6080.5,1913.41 6124.09,1913.41 6114.91,1904.23 R2_22_14.2@6114.91,1859 ; R9_22_14.2@6147.5,2480.41 v1(6147.5,2533) ; R4_23_14.2@6255.5,1913.41 6299.09,1913.41 6289.91,1904.23 R2_23_14.2@6289.91,1859 ; R9_23_14.2@6322.5,2480.41 v1(6322.5,2533) ; R4_22_15.2@6430.5,1913.41 6474.09,1913.41 6464.91,1904.23 R2_22_15.2@6464.91,1859 ; R9_22_15.2@6497.5,2480.41 v1(6497.5,2533) ; R4_23_15.2@6605.5,1913.41 6649.09,1913.41 6639.91,1904.23 R2_23_15.2@6639.91,1859 ; R9_23_15.2@6672.5,2480.41 v1(6672.5,2533)
  other v1: 1227.5,1909 1402.5,1909 1578.5,1909 1753.5,1909 1928.5,1909 2103.5,1909 2278.5,1909 2453.5,1909 2628.5,1909 2803.5,1909 2978.5,1909 3153.5,1909 3328.5,1909 3503.5,1909 3678.5,1909 3853.5,1909 4028.5,1909 4203.5,1909 4378.5,1909 4553.5,1909 4728.5,1909 4903.5,1909 5078.5,1909 5253.5,1909 5428.5,1909 5603.5,1909 5778.5,1909 5953.5,1909 6128.5,1909 6303.5,1909 6478.5,1909 6653.5,1909
pads on no net: P2.33 P2.34 P2.A2 P2.A3 P2.A4 P2.A6 P2.A7 P2.A9 P2.A10 P2.A11 P2.A12 P2.A14 P2.A15 P2.A16 P2.A17 P2.A18 P2.A20 P2.A21 P2.A22 P2.A23 P2.A25 P2.A26 P2.A27 P2.A28 P2.A29 P2.A30 P2.A31

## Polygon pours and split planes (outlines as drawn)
GND on GND (split plane): 6854.61,1020.39 1020.39,1020.39 1020.39,3529.61 6854.61,3529.61
VCC on VCC (split plane): 6854.61,1020.39 1020.39,1020.39 1020.39,3529.61 6854.61,3529.61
